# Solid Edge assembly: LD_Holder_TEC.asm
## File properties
Author: hhakima
Template: Normal.asm
Last saved by: hhakima
Revision: 5
Application: Solid Edge
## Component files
Part - Diode Holder.par
Part - Laser Diode.par
Part - TEC.par
Part - Collimator Tube.par
Part - Collimator Lens.par
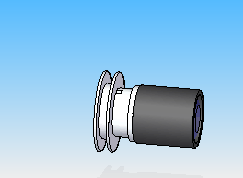
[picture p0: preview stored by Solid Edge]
